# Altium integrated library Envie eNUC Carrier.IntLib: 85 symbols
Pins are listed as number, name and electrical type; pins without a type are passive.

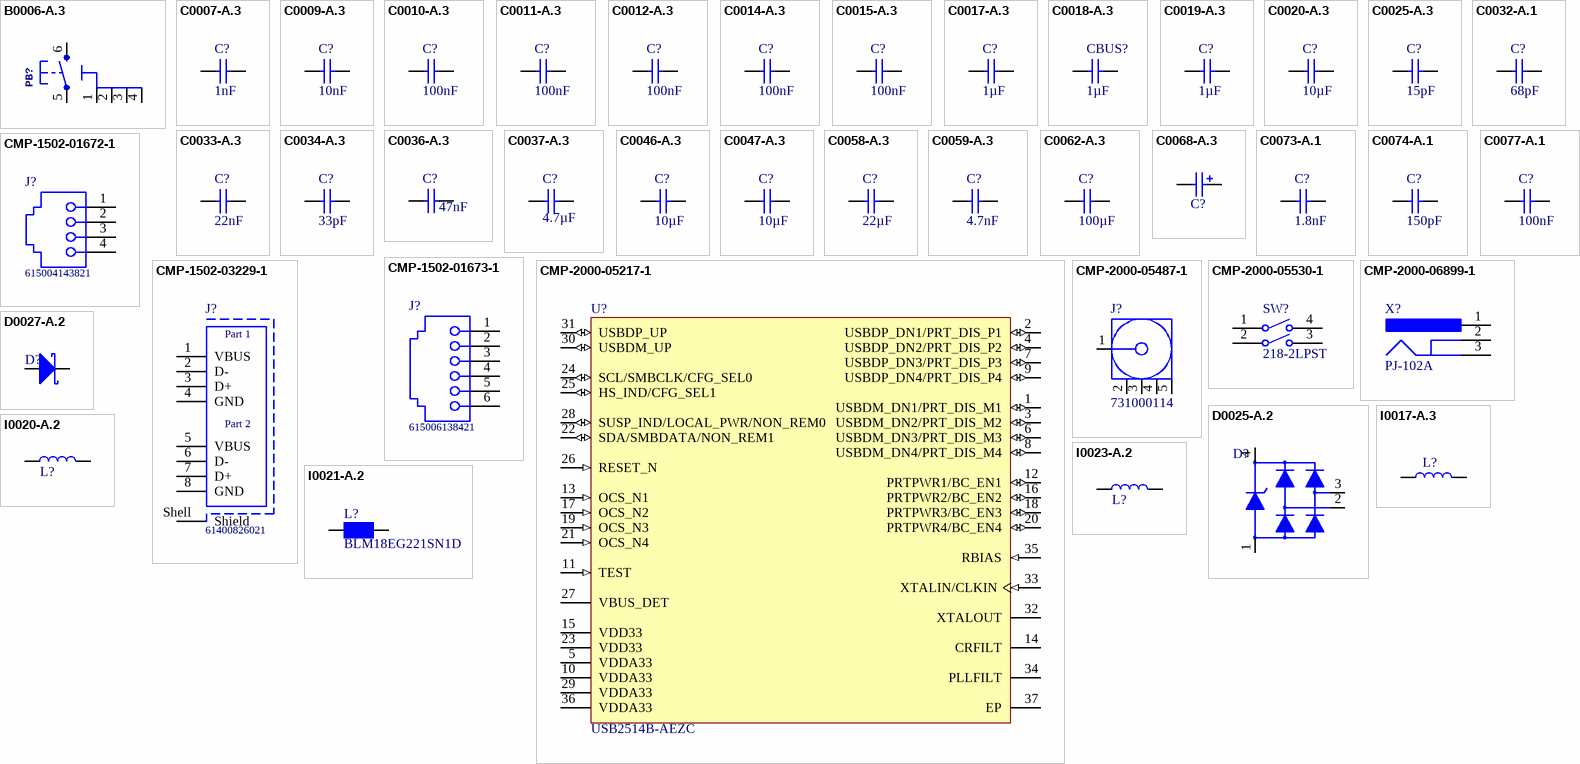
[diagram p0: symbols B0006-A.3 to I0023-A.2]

## B0006-A.3
designator PB?, comment PTS820J25KSMTRLFS  (value not drawn)
PUSHBUTTON SMD PTS820 NO HOLES; Manufacturer: C&K; Manufacturer: ITT C&K; Code Arduino: A5506; Actuator Type: Standard; Mechanical Life: 100000Cycles
footprint C&K_PTS820_NO_HOLES-1
pins: 1 (power), 2 (power), 3 (power), 4 (power), 5 1, 6 2

## C0007-A.3
designator C?, comment value 1nF  (hidden comment: C0402C100K5RACTU)
CAP CHIP 0402 1nF 50V X7R 10%; Manufacturer: KEMET; Manufacturer: Murata; Manufacturer Part Number: GRM155R71H102KA01D; Code Arduino: 2321
footprint CAP-0402 (Chip Capacitor, 2-Leads, Body  0402 (in) 1005 (mm), IPC Medium Density)
pins: 1, 2

## C0009-A.3
designator C?, comment value 10nF  (hidden comment: C0402C103K5RACTU)
CAP CHIP 0402 10nF 50V X7R 10%; Manufacturer: KEMET; Manufacturer: AVX; Manufacturer Part Number: 4025C103KAT2A; Code Arduino: 0165
footprint CAP-0402 (Chip Capacitor, 2-Leads, Body  0402 (in) 1005 (mm), IPC Medium Density)
pins: 1, 2

## C0010-A.3
designator C?, comment value 100nF  (hidden comment: C0402C104K8RACTU)
CAP CHIP 0402 100nF 10V X7R 10%; Manufacturer: AVX; Code Arduino: 0132
footprint CAP-0402 (Chip Capacitor, 2-Leads, Body  0402 (in) 1005 (mm), IPC Medium Density)
pins: 1, 2

## C0011-A.3
designator C?, comment value 100nF  (hidden comment: C0402C104K8PACTU)
CAP CHIP 0402 100nf 10V X5R 10%; Manufacturer: KEMET; Manufacturer: Kyocera AVX; Manufacturer Part Number: 0402ZD104KAT2A; Code Arduino: 0132
footprint CAP-0402 (Chip Capacitor, 2-Leads, Body  0402 (in) 1005 (mm), IPC Medium Density)
pins: 1, 2

## C0012-A.3
designator C?, comment value 100nF  (hidden comment: C0402C104K4RACTU)
CAP CHIP 0402 100nF 16V X7R 10%; Manufacturer: KEMET; Manufacturer: Kyocera AVX; Manufacturer Part Number: 0402YC104KAT2A; Code Arduino: 0132
footprint CAP-0402 (Chip Capacitor, 2-Leads, Body  0402 (in) 1005 (mm), IPC Medium Density)
pins: 1, 2

## C0014-A.3
designator C?, comment value 100nF  (hidden comment: C0402C104K3PACTU)
CAP CHIP 0402 100nF 25V X5R 10%; Manufacturer: KEMET; Manufacturer: Kyocera AVX; Manufacturer Part Number: 04023D104KAT2A; Code Arduino: 0132
footprint CAP-0402 (Chip Capacitor, 2-Leads, Body  0402 (in) 1005 (mm), IPC Medium Density)
pins: 1, 2

## C0015-A.3
designator C?, comment value 100nF  (hidden comment: GRM155R61H104KE19D)
CAP CHIP 0402 100nF 50V X5R 10%; Manufacturer: Murata; Code Arduino: A5141
footprint CAP-0402 (Chip Capacitor, 2-Leads, Body  0402 (in) 1005 (mm), IPC Medium Density)
pins: 1, 2

## C0017-A.3
designator C?, comment value 1µF  (hidden comment: C0402C105K8PACTU)
CAP CHIP 0402 1uF 10V X5R 10%; Manufacturer: KEMET; Manufacturer: AVX; Manufacturer Part Number: GRM155R61A105KE15D; Code Arduino: 0133
footprint CAP-0402 (Chip Capacitor, 2-Leads, Body  0402 (in) 1005 (mm), IPC Medium Density)
pins: 1, 2

## C0018-A.3
designator CBUS?, comment value 1µF  (hidden comment: C0402C105K4PACTU)
CAP CHIP 0402 1uF 16V X5R 10%; Manufacturer: KEMET; Manufacturer: Kyocera AVX; Manufacturer Part Number: 0402YD105KAT2A; Code Arduino: 0133
footprint CAP-0402 (Chip Capacitor, 2-Leads, Body  0402 (in) 1005 (mm), IPC Medium Density)
pins: 1, 2

## C0019-A.3
designator C?, comment value 1µF  (hidden comment: C0402C105M9PACTU)
CAP CHIP 0402 1uF 6V3 X5R 20%; Manufacturer: KEMET; Manufacturer: Kyocera AVX; Manufacturer Part Number: 04026D105MAT4A; Voltage: 6.3V; Code Arduino: 0133
footprint CAP-0402 (Chip Capacitor, 2-Leads, Body  0402 (in) 1005 (mm), IPC Medium Density)
pins: 1, 2

## C0020-A.3
designator C?, comment value 10µF  (hidden comment: GRM155R60G106ME44D)
CAP CHIP 0402 10UF 4V X5R 20%; Manufacturer: Murata; Code Arduino: 0132
footprint CAP-0402 (Chip Capacitor, 2-Leads, Body  0402 (in) 1005 (mm), IPC Medium Density)
pins: 1, 2

## C0025-A.3
designator C?, comment value 15pF  (hidden comment: C0402C150J5GACTU)
CAP CHIP 0402 15PF 50V C0G 5%; Manufacturer: Murata; Code Arduino: A5498
footprint CAP-0402 (Chip Capacitor, 2-Leads, Body  0402 (in) 1005 (mm), IPC Medium Density)
pins: 1, 2

## C0032-A.1
designator C?, comment value 68pF  (hidden comment: 04025A680JAT2A)
CAP CHIP 0402 68pF C0G 50V 5%; Manufacturer: AVX; Manufacturer: Kyocera AVX; Code Arduino: A5496
footprint CAP-0402 (Chip Capacitor, 2-Leads, Body  0402 (in) 1005 (mm), IPC Medium Density)
pins: 1, 2

## C0033-A.3
designator C?, comment value 22nF  (hidden comment: CL05B223KP5NNNC)
CAP CHIP 0402 22NF 10V X7R 10%; Manufacturer: Samsung Electro-Mechanics; Manufacturer: Samsung; Code Arduino: C0033
footprint CAP-0402 (Chip Capacitor, 2-Leads, Body  0402 (in) 1005 (mm), IPC Medium Density)
pins: 1, 2

## C0034-A.3
designator C?, comment value 33pF  (hidden comment: GRM1555C1H330JA01D)
CAP CHIP 0402 33PF 50V C0G 5%; Manufacturer: Murata; Code Arduino: A5494
footprint CAP-0402 (Chip Capacitor, 2-Leads, Body  0402 (in) 1005 (mm), IPC Medium Density)
pins: 1, 2

## C0036-A.3
designator C?, comment value 47nF  (hidden comment: GRM155R61H473KE14D)
CAP CHIP 0402 47nF 50V X5R 10%; Manufacturer: Murata; Code Arduino: 2216
footprint CAP-0402 (Chip Capacitor, 2-Leads, Body  0402 (in) 1005 (mm), IPC Medium Density)
pins: 1, 2

## C0037-A.3
designator C?, comment value 4.7µF  (hidden comment: GRM155R60J475ME47D)
CAP CHIP 0402 4.7uF 6V3 X5R 20%; Manufacturer: Murata; Code Arduino: 0833; Voltage: 6.3V
footprint CAP-0402 (Chip Capacitor, 2-Leads, Body  0402 (in) 1005 (mm), IPC Medium Density)
pins: 1, 2

## C0046-A.3
designator C?, comment value 10µF  (hidden comment: CC0603MRX5R5BB106)
CAP CHIP 0603 10uF 6V3 X5R 20% Bob; Manufacturer: Yageo; Voltage: 6.3V; Code Arduino: A5193
footprint CAP-0603 (Chip Capacitor, Body 0603 imperial,1.6x0.8mm, IPC High Density)
pins: 1, 2

## C0047-A.3
designator C?, comment value 10µF  (hidden comment: GRM188R61E106MA73J)
CAP CHIP 0603 10uF 25V X5R 20%; Manufacturer: Murata; Manufacturer: Samsung; Manufacturer Part Number: CL10A226MPCNUBE; Manufacturer Part Number: GRM188R61A226ME15D; Code Arduino: 2213
footprint CAP-0603 (Chip Capacitor, Body 0603 imperial,1.6x0.8mm, IPC High Density)
pins: 1, 2

## C0058-A.3
designator C?, comment value 22µF  (hidden comment: GRM219R61C226ME15K)
CAP CHIP 0805 22uF 16V X5R 20%; Manufacturer: Murata; Manufacturer: Samsung; Manufacturer Part Number: CL21A226MAQNNNE; Code Arduino: 2233
footprint CAP-0805 (Chip Capacitor, Body 0805 imperial, 2.0x1.2mm, IPC Medium Density)
pins: 1, 2

## C0059-A.3
designator C?, comment value 4.7nF  (hidden comment: C0805C472KDRACTU)
CAP CHIP 0805 4.7nF 1000V X7R 10%; Manufacturer: KEMET; Voltage: 1kV; Code Arduino: 0689
footprint CAP-0805 (Chip Capacitor, Body 0805 imperial, 2.0x1.2mm, IPC Medium Density)
pins: 1, 2

## C0062-A.3
designator C?, comment value 100µF  (hidden comment: CL31A107MPHNNNE)
CAP CHIP 1206 100UF 10V X5R 20%; Manufacturer: Samsung; Code Arduino: A5503
footprint CAP-1206 (Chip Capacitor, 2-Leads, 1206 (in) 3216 (mm), IPC Medium Density)
pins: 1, 2

## C0068-A.3
designator C?, comment EEE-FT1A151AR  (value not drawn)
CAP ALUM 150UF 20% 10V SMD; Manufacturer: Panasonic; Value: 150µF; Code Arduino: 2248
footprint PANASONIC_C
pins: 1, 2

## C0073-A.1
designator C?, comment value 1.8nF  (hidden comment: C0402C182J3GAC7867)
CAP CHIP 0402 1.8NF 25V C0G 5%; Manufacturer: KEMET; Manufacturer Part Number: C0402C182J3GACTU; Code Arduino: C0073
footprint CAP-0402 (Chip Capacitor, 2-Leads, Body  0402 (in) 1005 (mm), IPC Medium Density)
pins: 1, 2

## C0074-A.1
designator C?, comment value 150pF  (hidden comment: GRM1555C1H151FA01D)
CAP CHIP 0402 150PF 50V C0G 1%; Manufacturer: Murata; Code Arduino: C0074
footprint CAP-0402 (Chip Capacitor, 2-Leads, Body  0402 (in) 1005 (mm), IPC Medium Density)
pins: 1, 2

## C0077-A.1
designator C?, comment value 100nF  (hidden comment: TMK107BJ105MAHT)
CAP CHIP 0603 1UF 25V X5R 20%; Manufacturer: Taiyo Yuden; Code Arduino: C0077
footprint CAP-0603 (Chip Capacitor, Body 0603 imperial,1.6x0.8mm, IPC High Density)
pins: 1, 2

## CMP-1502-01672-1
designator J?, comment 615004143821
Modular Jack WR-MJ, Tab Up, Plastic, Horizontal Entry, THT, 4P4C; Manufacturer: Wurth Elektronik; Manufacturer: Wurth Electronics; Compliance: Leadfree/RoHS; Contact Resistance: 20mOhm; Withstanding Voltage: 1000VAC; Rated Current: 1.5A; Port: 1x1; Working Voltage: 120VAC
footprint 615004143821 (Modular Jack Horizontal Plastic 4P4C Tab Up)
pins: 1, 2, 3, 4

## CMP-1502-01673-1
designator J?, comment 615006138421
Modular Jack WR-MJ, Tab Up, Plastic, Horizontal Entry, THT, 6P6C; Manufacturer: Wurth Elektronik; Manufacturer: Wurth Electronics; Contact Resistance: 20mOhm; Working Voltage: 120VAC; Withstanding Voltage: 1000VAC; Compliance: Leadfree/RoHS; Rated Current: 1.5A; Port: 1x1
footprint 615006138421 (Modular Jack Horizontal Plastic 6P6C Tab Up)
pins: 1, 2, 3, 4, 5, 6

## CMP-1502-03229-1
designator J?, comment 61400826021
USB 2.0 Type A Receptacle WR-COM, Stacked Horizontal, THT; Manufacturer: Wurth Elektronik; Manufacturer: Wurth Electronics; Contact Resistance: 20mOhm; Rated Current: 1.5A; Working Voltage: 30VAC
footprint 61400826021 (USB 2.0 Type A Horizontal Dual Stacked)
pins: 1 VBUS, 2 D-, 3 D+, 4 GND, 5 VBUS, 6 D-, 7 D+, 8 GND, Shell Shield

## CMP-2000-05217-1
designator U?, comment USB2514B-AEZC
USB 2.0 High-Speed Hub Controller, 4 Ports, 3 to 3.6 V, 0 to 85 degC, 36-Pin QFN, RoHS, Tray; Manufacturer: Microchip; Interface: I²CEEPROM,SMBus(2-Wire,I²C); Other Names: 638-1122; Voltage - Supply: 3V~3.6V; Current - Supply: 70mA
footprint MCHP-QFN-36_V (QFN, 36-Leads, Body 6.00x6.00mm, Pitch 0.50mm, Thermal Pad 3.70x3.70mm)
pins: 1 USBDM_DN1/PRT_DIS_M1 (io), 2 USBDP_DN1/PRT_DIS_P1 (io), 3 USBDM_DN2/PRT_DIS_M2 (io), 4 USBDP_DN2/PRT_DIS_P2 (io), 5 VDDA33 (power) "3.3 V Analog Power", 6 USBDM_DN3/PRT_DIS_M3 (io), 7 USBDP_DN3/PRT_DIS_P3 (io), 8 USBDM_DN4/PRT_DIS_M4 (io), 9 USBDP_DN4/PRT_DIS_P4 (io), 10 VDDA33 (power) "3.3 V Analog Power", 11 TEST (in) "Test Pin: treat as a no connect pin or connect to ground. No trace or signal should be routed or attached to this pin.", 12 PRTPWR1/BC_EN1 (io), 13 OCS_N1 (in) "Over-Current Sense: input from external current monitor indicating an overcurrent condition.", 14 CRFILT "VDD Core Regulator Filter Capacitor: this pin can have up to a 0.1 uF low-ESR capacitor to VSS, or be left unconnected.", 15 VDD33 (power) "3.3 V Digital Power", 16 PRTPWR2/BC_EN2 (io), 17 OCS_N2 (in) "Over-Current Sense: input from external current monitor indicating an overcurrent condition.", 18 PRTPWR3/BC_EN3 (io), 19 OCS_N3 (in) "Over-Current Sense: input from external current monitor indicating an overcurrent condition.", 20 PRTPWR4/BC_EN4 (io), 21 OCS_N4 (in) "Over-Current Sense: input from external current monitor indicating an overcurrent condition.", 22 SDA/SMBDATA/NON_REM1 (io), 23 VDD33 (power) "3.3 V Digital Power", 24 SCL/SMBCLK/CFG_SEL0 (io), 25 HS_IND/CFG_SEL1 (io), 26 RESET_N (in) "RESET Input: the system can reset the chip by driving this input low. The minimum active low pulse is 1 us.", 27 VBUS_DET (power) "Detect Upstream VBUS Power: detects the state of the upstream VBUS power. The SMSC hub monitors VBUS_DET to determine when to assert the internal D+ pull-up resistor: (signaling a connect event). When designing a detachable (See Datasheet)", 28 SUSP_IND/LOCAL_PWR/NON_REM0 (io), 29 VDDA33 (power) "3.3 V Analog Power", 30 USBDM_UP (io) "USB Data: connect to the upstream USB bus data signals (host, port, or upstream hub).", 31 USBDP_UP (io) "USB Data: connect to the upstream USB bus data signals (host, port, or upstream hub).", 32 XTALOUT "Crystal Output: this is the other terminal of the crystal circuit with 1.2 V p-p output and a weak (< 1mA) driving strength. When an external clock source is used to drive XTALIN/CLKIN, leave this pin unconnected, or use (See Datasheet)", 33 XTALIN/CLKIN (in), 34 PLLFILT "PLL Regulator Filter Capacitor: this pin can have up to a 0.1 uF low-ESR capacitor to VSS, or be left unconnected.", 35 RBIAS (in) "USB Transceiver Bias: a 12.0 kohm (+/- 1%) resistor is attached from ground to this pin to set the transceiver’s internal bias settings.", 36 VDDA33 (power) "3.3 V Analog Power", 37 EP (power) "Ground Pad/ePad: the package slug is the only VSS for the device and must be tied to ground with multiple vias."

## CMP-2000-05487-1
designator J?, comment 731000114
SMA Right-Angle PCB Jack Receptacle, Brass Body, Gold Plated, 50 Ohm, 5-Pin THD, RoHS, Tray; Manufacturer: Molex; Manufacturer Part Number: 73100-0114
footprint MOLX-731000114_V (Connector, 5-Leads, Body 14.8x6.35mm, Pitch 2.54mm)
pins: 1, 2, 3, 4, 5

## CMP-2000-05530-1
designator SW?, comment 218-2LPST
Half Pitch DIP Switch Auto Placeable, 25 mA, 24 V, -55 to 85 degC, 4-Pin SMD, RoHS, Tube; Manufacturer: CTS Corporation; Manufacturer: CTS; Voltage Rating: 24VDC; Number of Positions: 2; Online Catalog: 218Series; Actuator Type: Slide(Standard); Washable: Yes; Pitch: 0.050"(1.27mm),Half; 3D Model: 218Series2Pole.stp; Catalog Drawings: 218-2218SeriesFootprint218SeriesEnd; Other Names: 2182LPSTCT2182LPST; Electrical Life: 1,000Cycles; Current Rating: 25mA; Actuator Level: Flush,Recessed; Circuit: SPST
footprint CTS-218-2LPST_V (SMD, 4-Leads, Body 5.8x3.71mm, Pitch 1.27mm)
pins: 1, 2, 3, 4

## CMP-2000-06899-1
designator X?, comment PJ-102A
DC Power Jack, 2.5 A, -25 to 85 degC, 3-Pin THD, RoHS; Manufacturer 1: CUIInc.; Insulation Resistance: 50MOhms; Current Rating: 2.5A; Inside Contact Diameter: 2mm; Outside Contact Diameter: 6.5mm; Brand: CUI; Mounting Angle: Right; Voltage Rating: 24V
footprint CUI-PJ-102A_V (THD, 3-Leads, Body 14.4x9mm, Pitch 3mm)
pins: 1, 2, 3

## D0025-A.2
designator D?, comment Diode TVS array  (value not drawn)
TVS ARRAY 4LIN.8kV 1pF SOT143B; Manufacturer: Nexperia; Part Number: PRTR5V0U2X,215; Device Type: ESD protection; Code Arduino: 2209
footprint SOT190P230X110-4N
pins: 1, 2, 3, 4

## D0027-A.2
designator D?, comment PESD0402-140CT-ND  (value not drawn)
DIODE TVS SMD 0402 14V 40V; Manufacturer: Littelfuse Inc; Code Arduino: 2280; Device Type: ESD protection
footprint 0402 (Chip Resistor, 2-Leads, Body  0402 (in) 1005 (mm), IPC Medium Density)
pins: A, C

## I0017-A.3
designator L?, comment SRP4020TA-2R2M  (value not drawn)
IND FIXED 2.2UH 4A 61 MOHM SMD; Manufacturer: Bourns; Code Arduino: 2218; Device Type: Inductor
footprint SRP4020
pins: 1, 2

## I0020-A.2
designator L?, comment LQG15HS68NJ02D  (value not drawn)
IND CHIP 0402 68NH 250MA 5%; Manufacturer: Murata; Device Type: Inductor; Code Arduino: A5499
footprint 0402 (Chip Inductor, 2-Leads, Body  0402 (in) 1005 (mm), IPC Medium Density)
pins: 1, 2

## I0021-A.2
designator L?, comment BLM18EG221SN1D
FERRITE SMD 0603 220 OHM 2A; Manufacturer: Murata; Impedance: 220µH; Code Arduino: A5489; Test Frequency: 100MHz; Tolerance: 25%; DC Resistance (DCR): 50mR
footprint L-0603 (Chip Inductor - Body 0603 imperial,1.6x0.8mm, IPC High Density)
pins: 1, 2

## I0023-A.2
designator L?, comment LQG15HN39NJ02D  (value not drawn)
IND CHIP 0402 39NH; Manufacturer: Murata; Code Arduino: A5497; Current: 250mA; Device Type: Inductor
footprint 0402 (Chip Inductor, 2-Leads, Body  0402 (in) 1005 (mm), IPC Medium Density)
pins: 1, 2

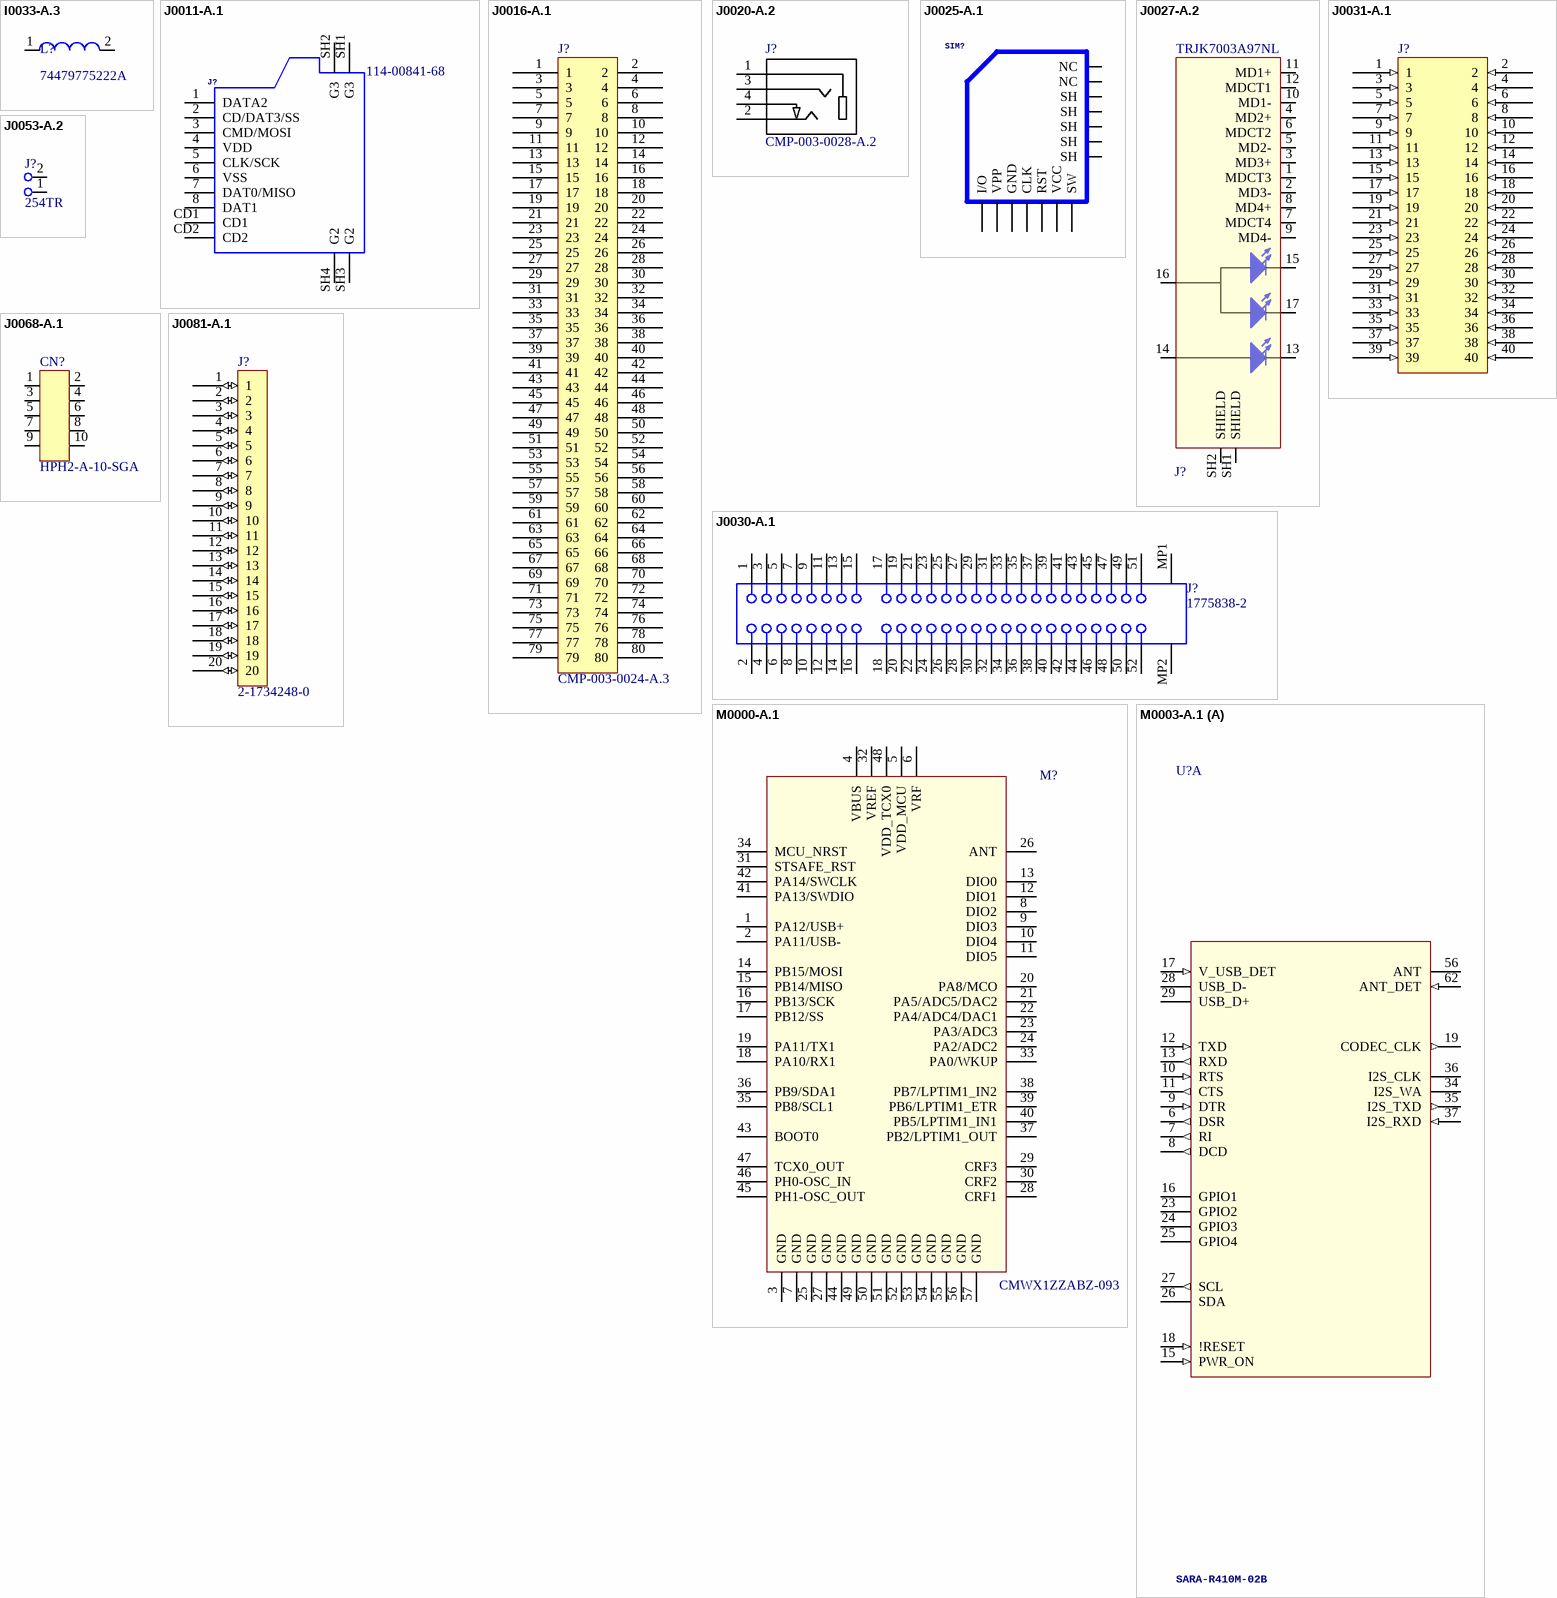
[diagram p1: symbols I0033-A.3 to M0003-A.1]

## I0033-A.3
designator L?, comment 74479775222A
IND FIXED 2.2UH; Manufacturer: Wurth Electronics; Manufacturer: Bourns; Manufacturer Part Number: CVH201205-2R2M; Device Type: Inductor; Code Arduino: I0033
footprint INDC2314X10N (Chip Inductor, 2-Leads, Body 2,35x1,45mm, IPC Medium Density)
pins: 1, 2

## J0011-A.1
designator J?, comment 114-00841-68
CONN Micro SD; Manufacturer: Amphenol; Manufacturer: Amphenol Commercial; Manufacturer Part Number: 1140084168; Code Arduino: A5328
footprint AMPHENOL_114-00841-68
pins: 1 DATA2, 2 CD/DAT3/SS, 3 CMD/MOSI, 4 VDD (power), 5 CLK/SCK, 6 VSS (power), 7 DAT0/MISO, 8 DAT1, CD1, CD2, SH1 G3, SH2 G3, SH3 G2, SH4 G2

## J0016-A.1
designator J?, comment CMP-003-0024-A.3
CONN RCPT 80POS 0.4MM SMD GOLD; Gender: Receptacle
footprint DF40HC(3.5)-80DS-0.4V(51)-Footprint-1
pins: 1, 2, 3, 4, 5, 6, 7, 8, 9, 10, 11, 12, 13, 14, 15, 16, 17, 18, 19, 20, 21, 22, 23, 24, 25, 26, 27, 28, 29, 30, 31, 32, 33, 34, 35, 36, 37, 38, 39, 40, 41, 42, 43, 44, 45, 46, 47, 48, 49, 50, 51, 52, 53, 54, 55, 56, 57, 58, 59, 60, 61, 62, 63, 64, 65, 66, 67, 68, 69, 70, 71, 72, 73, 74, 75, 76, 77, 78, 79, 80

## J0020-A.2
designator J?, comment CMP-003-0028-A.2
CONN JACK STEREO 3.5MM SMD R/A; Manufacturer: CUI; Manufacturer Part Number: SJ-3524-SMT-TR; Gender: Female; Code Arduino: J0020
footprint SJ-3524-SMT-TR-Footprint-1
pins: 1, 2, 3, 4

## J0025-A.1
designator SIM?, comment 2199337-5  (value not drawn)
CONN MICROSIM CARD HOLDER; Manufacturer: TE; Manufacturer: TE Connectivity AMP; Code Arduino: A5504
footprint MICROSIM8
pins: CLK, GND, IO I/O, NC1 NC, NC2 NC, RST, SH1 SH, SH2 SH, SH3 SH, SH4 SH, SH5 SH, SW, VCC, VPP

## J0027-A.2
designator J?, comment TRJK7003A97NL
CONN ETHERNET 1GIGABIT; Manufacturer: TRXCOM; Code Arduino: J0027
footprint TRJK0071AWNL -Footprint-2
pins: 1 MDCT3, 2 MD3-, 3 MD3+, 4 MD2+, 5 MD2-, 6 MDCT2, 7 MDCT4, 8 MD4+, 9 MD4-, 10 MD1-, 11 MD1+, 12 MDCT1, 13, 14, 15, 16, 17, SH1 SHIELD, SH2 SHIELD

## J0030-A.1
designator J?, comment 1775838-2
CONN PCI EXP MINI FEMALE 52POS; Manufacturer: TE Connectivity; Manufacturer: TE Connectivity AMP; Code Arduino: J0030; PCB Mount Retention: Without; Connector Type: Receptacle; High Temperature Housing: Yes; Stackable: No; PCB Mounting Orientation: Vertical; Pitch: 0.8mm; Stack Height: 5.6mm; Row Spacing: 0.031inch; Number of Positions: 52
footprint 1775838-2-Footprint-1
pins: 1, 2, 3, 4, 5, 6, 7, 8, 9, 10, 11, 12, 13, 14, 15, 16, 17, 18, 19, 20, 21, 22, 23, 24, 25, 26, 27, 28, 29, 30, 31, 32, 33, 34, 35, 36, 37, 38, 39, 40, 41, 42, 43, 44, 45, 46, 47, 48, 49, 50, 51, 52, MP1 53, MP2 54

## J0031-A.1
designator J?, comment CMP-003-0051-A.3  (value not drawn)
CONN BOARD STACKER HDR 40 POS 1.27mm ST SMD; Manufacturer: Samtec; Manufacturer Part Number: FW-20-05-G-D-254-150; Gender: Male
footprint FW-20-05-G-D-254-150-Footprint-1
pins: 1 (in), 2 (in), 3 (in), 4 (in), 5 (in), 6 (in), 7 (in), 8 (in), 9 (in), 10 (in), 11 (in), 12 (in), 13 (in), 14 (in), 15 (in), 16 (in), 17 (in), 18 (in), 19 (in), 20 (in), 21 (in), 22 (in), 23 (in), 24 (in), 25 (in), 26 (in), 27 (in), 28 (in), 29 (in), 30 (in), 31 (in), 32 (in), 33 (in), 34 (in), 35 (in), 36 (in), 37 (in), 38 (in), 39 (in), 40 (in)

## J0053-A.2
designator J?, comment 254TR
CONN BATTERY HOLDER 18650 CLIP SMT; Manufacturer: Keystone Electronics; Code Arduino: J0053
footprint 254TR-Footprint-1
pins: 1 -, 2 GND

## J0068-A.1
designator CN?, comment HPH2-A-10-SGA
CONN CONN STRIP 1,27 M/2/D 10v AuF H6,3; Manufacturer: Adam Tech; Code Arduino: 0171
footprint PINHEAD_2X05_127
pins: 1, 2, 3, 4, 5, 6, 7, 8, 9, 10

## J0081-A.1
designator J?, comment 2-1734248-0
CONN FPC VERT 20POS 1.00MM SMD; Manufacturer: TE Connectivity; Contact Location: Bottom; PCB Mounting Orientation: Vertical; Sealable: No (Without); Shielding: Unshielded; Wire/Cable Type: Flat Flex; Number of Contacts: 20; Code Arduino: J0081; PCB Mount Retention: With; Pitch: 0.039inch; Voltage Rating: 125V; Connector Type: Receptacle,Connector,Socket; Contact Current Rating: 1A; Shrouded: Yes (With); Gender: Male; Connector System: Flex-to-Board
footprint 2-1734248-0-Footprint-1
pins: 1 (io), 2 (io), 3 (io), 4 (io), 5 (io), 6 (io), 7 (io), 8 (io), 9 (io), 10 (io), 11 (io), 12 (io), 13 (io), 14 (io), 15 (io), 16 (io), 17 (io), 18 (io), 19 (io), 20 (io)

## M0000-A.1
designator M?, comment CMWX1ZZABZ-093
MODULE LoRa; Manufacturer: Murata; Code Arduino: A5491
footprint CMWX1ZZABZ
pins: 1 PA12/USB+, 2 PA11/USB-, 3 GND, 4 VBUS, 5 VDD_MCU, 6 VRF, 7 GND, 8 DIO2, 9 DIO3, 10 DIO4, 11 DIO5, 12 DIO1, 13 DIO0, 14 PB15/MOSI, 15 PB14/MISO, 16 PB13/SCK, 17 PB12/SS, 18 PA10/RX1, 19 PA11/TX1, 20 PA8/MCO, 21 PA5/ADC5/DAC2, 22 PA4/ADC4/DAC1, 23 PA3/ADC3, 24 PA2/ADC2, 25 GND, 26 ANT, 27 GND, 28 CRF1, 29 CRF3, 30 CRF2, 31 STSAFE_RST, 32 VREF, 33 PA0/WKUP, 34 MCU_NRST, 35 PB8/SCL1, 36 PB9/SDA1, 37 PB2/LPTIM1_OUT, 38 PB7/LPTIM1_IN2, 39 PB6/LPTIM1_ETR, 40 PB5/LPTIM1_IN1, 41 PA13/SWDIO, 42 PA14/SWCLK, 43 BOOT0, 44 GND, 45 PH1-OSC_OUT, 46 PH0-OSC_IN, 47 TCX0_OUT, 48 VDD_TCX0, 49 GND, 50 GND, 51 GND, 52 GND, 53 GND, 54 GND, 55 GND, 56 GND, 57 GND

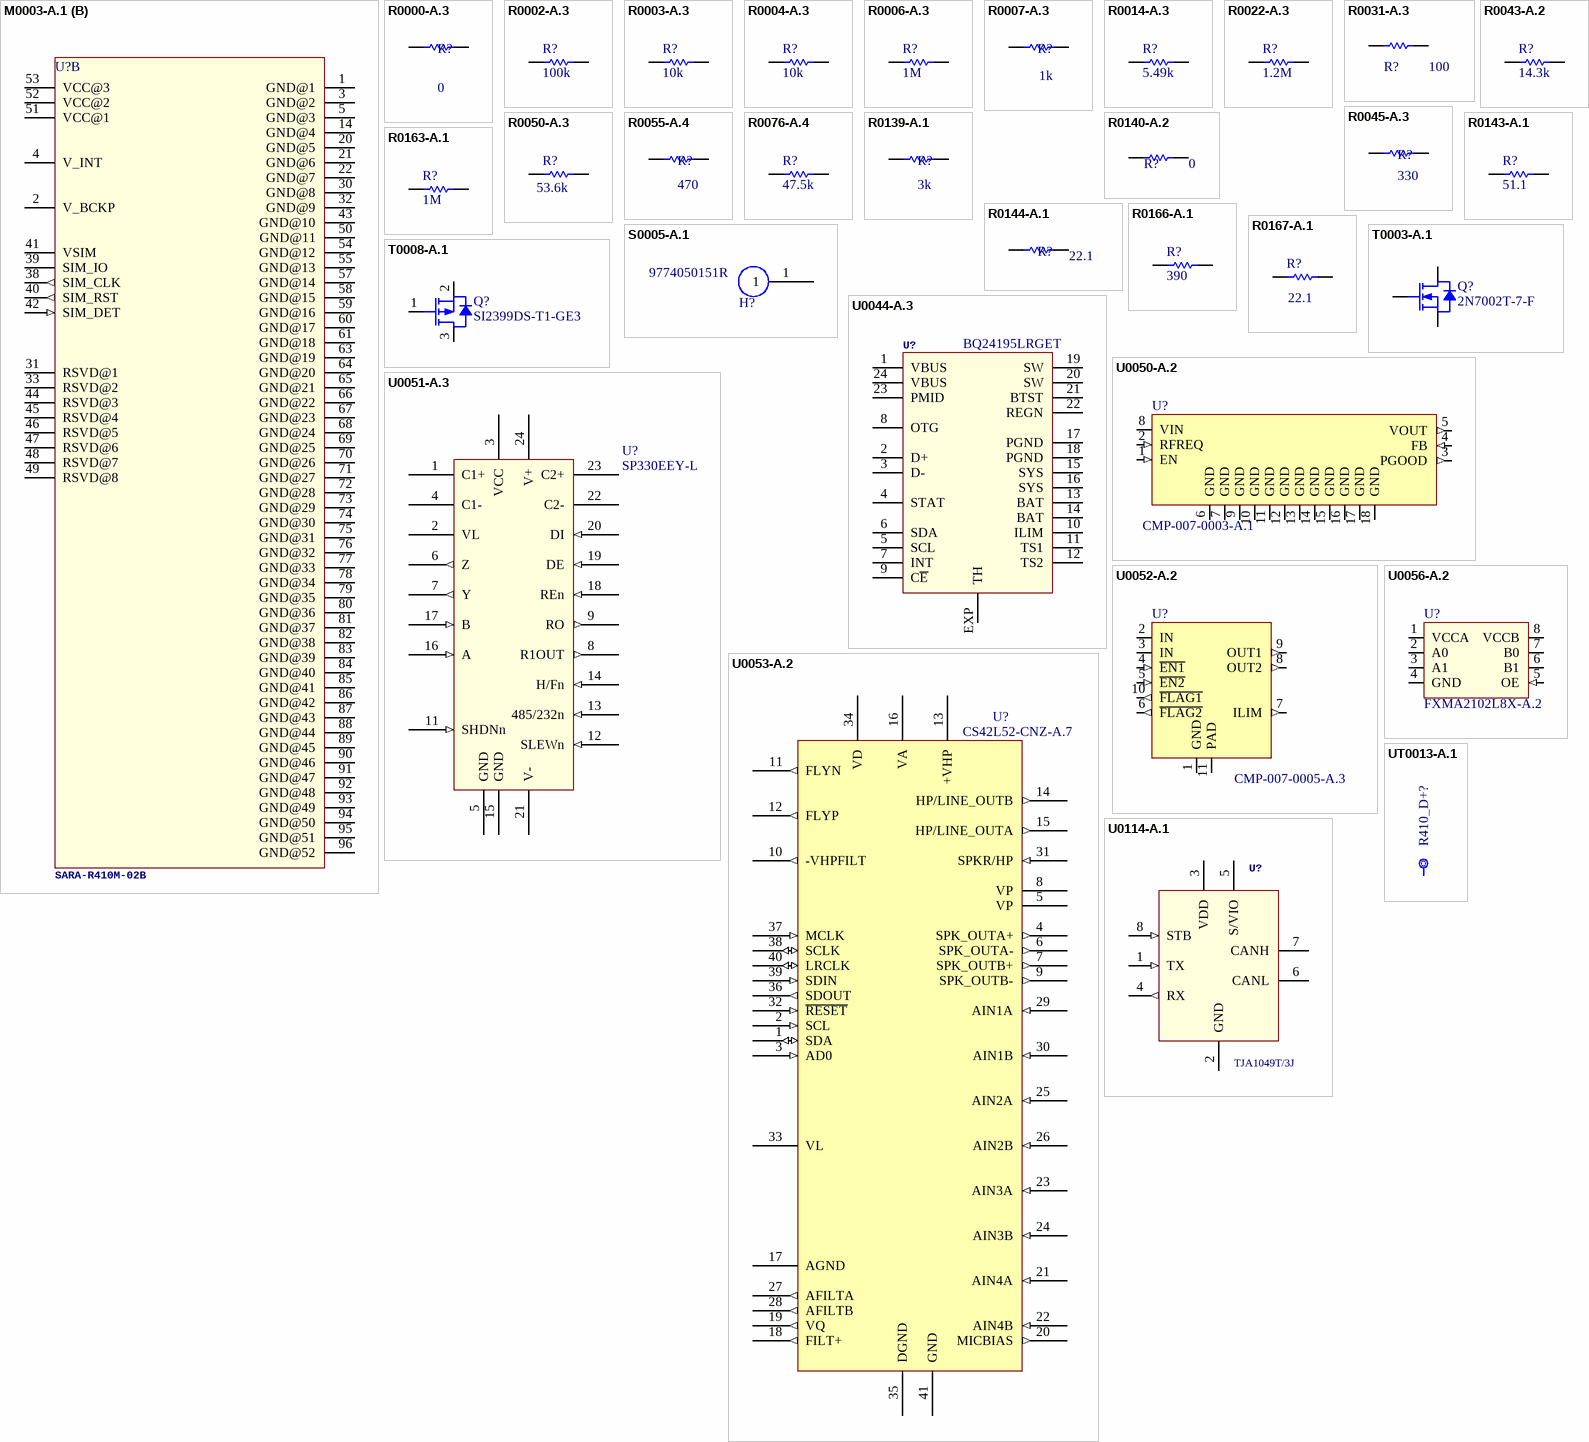
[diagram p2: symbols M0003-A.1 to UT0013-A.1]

## M0003-A.1
designator U?, comment SARA-R410M-02B
MODULE RF TXRX CELL 4G LTE CATM1/NB-IOT; Manufacturer: UBlox; Manufacturer: u-blox
footprint SARA-96
part A pins: 6 DSR (out), 7 RI (out), 8 DCD (out), 9 DTR (in), 10 RTS (in), 11 CTS (out), 12 TXD (in), 13 RXD (out), 15 PWR_ON (in), 16 GPIO1, 17 V_USB_DET (in), 18 !RESET (in), 19 CODEC_CLK (out), 23 GPIO2, 24 GPIO3, 25 GPIO4, 26 SDA, 27 SCL (out), 28 USB_D-, 29 USB_D+, 34 I2S_WA, 35 I2S_TXD (out), 36 I2S_CLK, 37 I2S_RXD (in), 56 ANT, 62 ANT_DET (in)
part B pins: 1 GND@1 (power), 2 V_BCKP (power), 3 GND@2 (power), 4 V_INT (power), 5 GND@3 (power), 14 GND@4 (power), 20 GND@5 (power), 21 GND@6 (power), 22 GND@7 (power), 30 GND@8 (power), 31 RSVD@1, 32 GND@9 (power), 33 RSVD@2, 38 SIM_CLK (out), 39 SIM_IO, 40 SIM_RST (out), 41 VSIM (power), 42 SIM_DET (in), 43 GND@10 (power), 44 RSVD@3, 45 RSVD@4, 46 RSVD@5, 47 RSVD@6, 48 RSVD@7, 49 RSVD@8, 50 GND@11 (power), 51 VCC@1 (power), 52 VCC@2 (power), 53 VCC@3 (power), 54 GND@12 (power), 55 GND@13 (power), 57 GND@14 (power), 58 GND@15 (power), 59 GND@16 (power), 60 GND@17 (power), 61 GND@18 (power), 63 GND@19 (power), 64 GND@20 (power), 65 GND@21 (power), 66 GND@22 (power), 67 GND@23 (power), 68 GND@24 (power), 69 GND@25 (power), 70 GND@26 (power), 71 GND@27 (power), 72 GND@28 (power), 73 GND@29 (power), 74 GND@30 (power), 75 GND@31 (power), 76 GND@32 (power), 77 GND@33 (power), 78 GND@34 (power), 79 GND@35 (power), 80 GND@36 (power), 81 GND@37 (power), 82 GND@38 (power), 83 GND@39 (power), 84 GND@40 (power), 85 GND@41 (power), 86 GND@42 (power), 87 GND@43 (power), 88 GND@44 (power), 89 GND@45 (power), 90 GND@46 (power), 91 GND@47 (power), 92 GND@48 (power), 93 GND@49 (power), 94 GND@50 (power), 95 GND@51 (power), 96 GND@52 (power)

## R0000-A.3
designator R?, comment value 0  (hidden comment: CRCW04020000Z0EDC)
RES CHIP 0402 0R 1/16W; Manufacturer: Vishay; Manufacturer: Panasonic; Manufacturer Part Number: ERJ-S020R00X; Code Arduino: 0039; Tolerance: J; Power: 63mW
footprint RES-0402 (Chip Resistor, 2-Leads, Body  0402 (in) 1005 (mm), IPC Medium Density)
pins: 1, 2

## R0002-A.3
designator R?, comment value 100k  (hidden comment: CRCW0402100KJNED)
RES CHIP 0402 100K 5% 1/16W; Manufacturer: Vishay; Manufacturer: Panasonic; Manufacturer Part Number: ERJ-2GEJ104X; Power: 63mW; Code Arduino: 0134
footprint RES-0402 (Chip Resistor, 2-Leads, Body  0402 (in) 1005 (mm), IPC Medium Density)
pins: 1, 2

## R0003-A.3
designator R?, comment value 10k  (hidden comment: CRCW040210K0FKED)
RES CHIP 0402 10K 1% 1/16W; Manufacturer: Vishay; Manufacturer Part Number: CRCW0402-10K0FKED; Manufacturer: Panasonic; Manufacturer Part Number: ERJ-2RKF1002X; Power: 63mW; Code Arduino: 0136
footprint RES-0402 (Chip Resistor, 2-Leads, Body  0402 (in) 1005 (mm), IPC Medium Density)
pins: 1, 2

## R0004-A.3
designator R?, comment value 10k  (hidden comment: CRCW040210K0JNED)
RES CHIP 0402 10K 5% 1/16W; Manufacturer: Vishay; Manufacturer: Vishay Dale; Manufacturer: Panasonic; Manufacturer Part Number: ERJ-2GEJ103X; Code Arduino: 0136; Power: 63mW
footprint RES-0402 (Chip Resistor, 2-Leads, Body  0402 (in) 1005 (mm), IPC Medium Density)
pins: 1, 2

## R0006-A.3
designator R?, comment value 1M  (hidden comment: CRCW04021M00JNED)
RES CHIP 0402 1M 5% 1/16W; Manufacturer: Panasonic; Manufacturer Part Number: ERJ-2GEJ105X; Code Arduino: 0139; Power: 63mW
footprint RES-0402 (Chip Resistor, 2-Leads, Body  0402 (in) 1005 (mm), IPC Medium Density)
pins: 1, 2

## R0007-A.3
designator R?, comment value 1k  (hidden comment: CRCW04021K00FKEDC)
RES CHIP 0402 1K 1% 1/16W; Manufacturer: Vishay; Manufacturer: Panasonic; Manufacturer Part Number: ERJ-2RKF1001X; Power: 63mW; Code Arduino: 0140
footprint RES-0402 (Chip Resistor, 2-Leads, Body  0402 (in) 1005 (mm), IPC Medium Density)
pins: 1, 2

## R0014-A.3
designator R?, comment value 5.49k  (hidden comment: CRCW04025K49FKED)
RES CHIP 0402 5K49 1% 1/16W; Manufacturer: Vishay; Manufacturer: Panasonic; Manufacturer Part Number: ERJ-2RKF5491X; Code Arduino: 2197; Power: 63mW
footprint RES-0402 (Chip Resistor, 2-Leads, Body  0402 (in) 1005 (mm), IPC Medium Density)
pins: 1, 2

## R0022-A.3
designator R?, comment value 1.2M  (hidden comment: CRCW04021M20JNED)
RES CHIP 0402 1M2 5% 1/16W; Manufacturer: Vishay; Manufacturer: Panasonic; Manufacturer Part Number: ERJ-2GEJ125X; Manufacturer: Vishay Dale; Code Arduino: 2352; Power: 63mW
footprint RES-0402 (Chip Resistor, 2-Leads, Body  0402 (in) 1005 (mm), IPC Medium Density)
pins: 1, 2

## R0031-A.3
designator R?, comment value 100  (hidden comment: CRCW0402100RFKED)
RES CHIP 0402 100R 1% 1/16W; Manufacturer: Vishay; Manufacturer: Panasonic; Manufacturer Part Number: ERJ-2RKF1000X; Manufacturer: Vishay Dale; Power: 63mW; Code Arduino: A5359
footprint RES-0402 (Chip Resistor, 2-Leads, Body  0402 (in) 1005 (mm), IPC Medium Density)
pins: 1, 2

## R0043-A.2
designator R?, comment value 14.3k  (hidden comment: CRCW040214K3FKED)
RES CHIP 0402 14K3 1/16W 1%; Manufacturer: Vishay; Manufacturer: Panasonic; Manufacturer Part Number: ERJ-2RKF1432X; Power: 63mW; Code Arduino: R0043
footprint RES-0402 (Chip Resistor, 2-Leads, Body  0402 (in) 1005 (mm), IPC Medium Density)
pins: 1, 2

## R0045-A.3
designator R?, comment value 330  (hidden comment: CRCW0402330RJNED)
RES CHIP 0402 330R 5% 1/16W; Manufacturer: Vishay; Manufacturer: Panasonic; Manufacturer Part Number: ERJ-2GEJ331X; Manufacturer: Vishay Dale; Code Arduino: 2229; Power: 63mW
footprint RES-0402 (Chip Resistor, 2-Leads, Body  0402 (in) 1005 (mm), IPC Medium Density)
pins: 1, 2

## R0050-A.3
designator R?, comment value 53.6k  (hidden comment: CRCW040253K6FKED)
RES CHIP 0402 53.6K 1% 1/16W; Manufacturer: Vishay; Manufacturer: Panasonic; Manufacturer Part Number: ERJ-2RKF5362X; Power: 63mW; Code Arduino: A5313
footprint RES-0402 (Chip Resistor, 2-Leads, Body  0402 (in) 1005 (mm), IPC Medium Density)
pins: 1, 2

## R0055-A.4
designator R?, comment value 470  (hidden comment: CRCW0402470RJNED)
RES CHIP 0402 470R 5% 1/16W; Manufacturer: Vishay; Manufacturer: Vishay Dale; Manufacturer: Panasonic; Manufacturer Part Number: ERJ-2GEJ471X; Power: 63mW; Code Arduino: R0055; Tolerance: 1%
footprint RES-0402 (Chip Resistor, 2-Leads, Body  0402 (in) 1005 (mm), IPC Medium Density)
pins: 1, 2

## R0076-A.4
designator R?, comment value 47.5k  (hidden comment: CRCW040247K5FKED)
RES CHIP 0402 47K5 1% 1/16W; Manufacturer: Vishay; Manufacturer: Panasonic; Manufacturer Part Number: ERJ-2RKF4752X; Power: 63mW; Code Arduino: R0076
footprint RES-0402 (Chip Resistor, 2-Leads, Body  0402 (in) 1005 (mm), IPC Medium Density)
pins: 1, 2

## R0139-A.1
designator R?, comment value 3k  (hidden comment: CRCW04023K00JNED)
RES CHIP 0402 3k 5% 1/16W; Manufacturer: Vishay; Manufacturer: Vishay Dale; Manufacturer: Panasonic; Manufacturer Part Number: ERJ-2GEJ302X; Tolerance: 1%; Power: 63mW; Code Arduino: R0139
footprint RES-0402 (Chip Resistor, 2-Leads, Body  0402 (in) 1005 (mm), IPC Medium Density)
pins: 1, 2

## R0140-A.2
designator R?, comment value 0  (hidden comment: CRCW02010000Z0ED)
RES CHIP 0201 0R 1/20W 5%; Manufacturer: Vishay; Code Arduino: R0140; Power: 50mW
footprint RES-0201 (Chip Resistor, 2-Leads, Body 0201 (in) 0603 (mm) IPC Medium Density)
pins: 1, 2

## R0143-A.1
designator R?, comment value 51.1  (hidden comment: CRCW040251R1FKED)
RES CHIP 0402 51R1 1% 1/16W; Manufacturer: Yageo; Manufacturer: Panasonic; Manufacturer Part Number: ERJ-2RKF51R1X; Manufacturer: Vishay; Manufacturer Part Number: CRCW04025-1R1FKED; Power: 63mW; Code Arduino: R0143
footprint RES-0402 (Chip Resistor, 2-Leads, Body  0402 (in) 1005 (mm), IPC Medium Density)
pins: 1, 2

## R0144-A.1
designator R?, comment value 22.1  (hidden comment: CRCW040222R1FKED)
RES CHIP 0402 22R1 1% 1/16W; Manufacturer: Vishay; Manufacturer: Panasonic; Manufacturer Part Number: ERJ-2RKF2212X; Power: 63mW; Code Arduino: R0144
footprint RES-0402 (Chip Resistor, 2-Leads, Body  0402 (in) 1005 (mm), IPC Medium Density)
pins: 1, 2

## R0163-A.1
designator R?, comment value 1M  (hidden comment: CRCW06031M00FKEA)
RES CHIP 0603 1M 1% 1/10W; Manufacturer: Vishay; Manufacturer: Panasonic; Manufacturer Part Number: ERJ-3EKF1004V; Power: 100mW; Code Arduino: R0163
footprint RES-0603 (Chip Resistor - Body 0603 imperial,1.6x0.8mm, IPC High Density)
pins: 1, 2

## R0166-A.1
designator R?, comment value 390  (hidden comment: CRCW04022K00JNED)
RES CHIP 0402 2K 5% 1/16W; Manufacturer: Vishay; Manufacturer: Panasonic; Manufacturer Part Number: ERJ-2GEJ202X; Manufacturer: Vishay Dale; Tolerance: 1%; Power: 63mW; Code Arduino: R0166
footprint RES-0402 (Chip Resistor, 2-Leads, Body  0402 (in) 1005 (mm), IPC Medium Density)
pins: 1, 2

## R0167-A.1
designator R?, comment value 22.1  (hidden comment: RR0510P-123-D)
RES CHIP 0402 12K 0.5% 1/16W; Manufacturer: Susumu; Code Arduino: R0167; Power: 63mW
footprint RES-0402 (Chip Resistor, 2-Leads, Body  0402 (in) 1005 (mm), IPC Medium Density)
pins: 1, 2

## S0005-A.1
designator H?, comment 9774050151R
VERT STANDOFF SMD M2.5X0.45 STEEL 5MM; Manufacturer: Würth Elektronik; Manufacturer: Wurth Electronics; Threaded/Unthreaded: Threaded; Plating: Tin; Code Arduino: S0005; Outside Diameter: 0.201inch
footprint 9774050151R-Footprint-1
pins: 1

## T0003-A.1
designator Q?, comment 2N7002T-7-F
MOSFET N-CH 60V 115mA SOT523; Manufacturer: Diodes Inc.; Manufacturer: Diodes; Code Arduino: 2368; Device Type: Mosfet N-CH SMD
footprint SOT523
pins: D, G, S

## T0008-A.1
designator Q?, comment SI2399DS-T1-GE3
MOSFET P-CH 20V 6A SOT-23; Device Type: Mosfet P-CH SMD; Code Arduino: A5270
footprint SOT23
pins: 1 G, 2 S, 3 D

## U0044-A.3
designator U?, comment Part Number: BQ24195LRGET  (hidden comment: BQ24195LRGET-A.4)
IC BATT.CHRG.CTRL. VQFN24; Manufacturer: Texas Instruments; Code Arduino: 2201
footprint VQFN24
pins: 1 VBUS, 2 D+, 3 D-, 4 STAT, 5 SCL, 6 SDA, 7 INT, 8 OTG, 9 C~{E}, 10 ILIM, 11 TS1, 12 TS2, 13 BAT, 14 BAT, 15 SYS, 16 SYS, 17 PGND, 18 PGND, 19 SW, 20 SW, 21 BTST, 22 REGN, 23 PMID, 24 VBUS, EXP TH

## U0050-A.2
designator U?, comment CMP-007-0003-A.1
IC DC/DC POWER MODULE 36V 5A LGA18; Part Number: MPM3550E; Manufacturer: MPS; Code Arduino: U0050
footprint LGA18C100P6X4_1200X1200X360 (LGA, 18-Leads, Body 12.00x12.00mmx3.60mm, Pitch 1.00mm)
pins: 1 EN (in), 2 RFREQ (in), 3 PGOOD (out), 4 FB (in), 5 VOUT (out), 6 GND (power), 7 GND (power), 8 VIN (power), 9 GND (power), 10 GND (power), 11 GND (power), 12 GND (power), 13 GND (power), 14 GND (power), 15 GND (power), 16 GND (power), 17 GND (power), 18 GND (power)

## U0051-A.3
designator U?, comment Part Number: SP330EEY-L  (hidden comment: CMP-007-0004-A.4)
IC TXRX RS232/485 24TSSOP; Manufacturer: Maxlinear; Simplex/Duplex: Full Duplex; Data Rate: 20Mbps; Receiver Hysteresis: 25mV; Code Arduino: U0051; Device Type: Transceiver
footprint TSOP65P640X120-24N (TSOP, 24-Leads, Body 7,80x4,40mm, Pitch 0,65mm, IPC Medium Density)
pins: 1 C1+ (power), 2 VL (power), 3 VCC (power), 4 C1- (power), 5 GND (power), 6 Z (out), 7 Y (out), 8 R1OUT (out), 9 RO (out), 11 SHDNn (in), 12 SLEWn (in), 13 485/232n (in), 14 H/Fn (in), 15 GND (power), 16 A (in), 17 B (in), 18 REn (in), 19 DE (in), 20 DI (in), 21 V- (power), 22 C2- (power), 23 C2+ (power), 24 V+ (power)

## U0052-A.2
designator U?, comment CMP-007-0005-A.3
IC POWER SWITCH DUAL CHANNEL OCP; Manufacturer: ON Semiconductor; Part Number: NCP383LMUAJAATXG; Max Input Voltage: 5.5V; Min Input Voltage: 2.7V; Turn-Off Delay Time: 3ms; Number of Outputs: 2; Output Configuration: High Side; Turn-On Delay Time: 9ms; Interface: On/Off; Max Power Dissipation: 850mW; Code Arduino: U0052; On-State Resistance: 95mR; Max Output Current: 2.5A; Device Type: PWR SWITCH; Fault Protection: Over Temperature; Max Supply Current: 1uA
footprint PQFN50P300X300X55_HS-21L (PQFN, 20-Leads, Body 3.00x3.00mm, Pitch 0.50mm, Thermal Pad 1.69x2.59mm, IPC High Density)
pins: 1 GND (power), 2 IN (power), 3 IN (power), 4 ~{EN1} (in), 5 ~{EN2} (in), 6 ~{FLAG2} (out), 7 ILIM (out), 8 OUT2 (out), 9 OUT1 (out), 10 ~{FLAG1} (out), 11 PAD

## U0053-A.2
designator U?, comment CS42L52-CNZ-A.7
IC CODEC STER HDPN & SPKR 40QFN; Manufacturer: Cirrus Logic; Number of A/D Converters: 1; Operating Supply Voltage: 2.5V; Code Arduino: U0053; Interface: Serial,I2C,SPI; Resolution: 24b; Sampling Rate: 96KS/s
footprint QFN127P600-8N
pins: 1 SDA (io), 2 SCL (in), 3 AD0 (in), 4 SPK_OUTA+ (out), 5 VP (power), 6 SPK_OUTA- (out), 7 SPK_OUTB+ (out), 8 VP (power), 9 SPK_OUTB- (out), 10 -VHPFILT (out), 11 FLYN (out), 12 FLYP (out), 13 +VHP (power), 14 HP/LINE_OUTB (out), 15 HP/LINE_OUTA (out), 16 VA (power), 17 AGND (power), 18 FILT+ (out), 19 VQ (out), 20 MICBIAS (out), 21 AIN4A (in), 22 AIN4B (in), 23 AIN3A (in), 24 AIN3B (in), 25 AIN2A (in), 26 AIN2B (in), 27 AFILTA (out), 28 AFILTB (out), 29 AIN1A (in), 30 AIN1B (in), 31 SPKR/HP (in), 32 ~{RESET} (in), 33 VL (power), 34 VD (power), 35 DGND (power), 36 SDOUT (out), 37 MCLK (in), 38 SCLK (io), 39 SDIN (in), 40 LRCLK (io), 41 GND (power)

## U0056-A.2
designator U?, comment FXMA2102L8X-A.2
IC TRANSLATOR/BUFF/REPEAT 8-MLP; Manufacturer: On Semiconductor; Manufacturer: ON Semiconductor / Fairchild; Max Power Dissipation: 129mW; Quiescent Current: 5uA; Device Type: TRANSLATOR BIDIR; Code Arduino: U0056; Number of Bits: 2; Logic Function: Translator,Buffer; Max Supply Voltage: 5.5V; Min Supply Voltage: 1.65V; Low Level Output Current: 6mA; Output Type: Voltage; Frequency: 50MHz; Propagation Delay: 105ns; Turn-On Delay Time: 1ns; Nominal Supply Current: 2uA
footprint MicroPak-8 (8- Lead MicroPak™, 1.6 mm Wide)
pins: 1 VCCA (power), 2 A0 (io), 3 A1 (io), 4 GND (power), 5 OE (in), 6 B1 (io), 7 B0 (io), 8 VCCB (power)

## U0114-A.1
designator U?, comment TJA1049T/3J
IC CAN TRANSCEIVER 1Mbps STBY 5.25V SOIC8; Manufacturer: NXP; Manufacturer: NXP Semiconductors; Code Arduino: U0114; Data Rate: 5Mbps; Number of Transceivers: 1; Simplex/Duplex: Half Duplex; Receiver Hysteresis: 300mV; Min Supply Voltage: 4.75V
footprint TJA1049T_3J-Footprint-1
pins: 1 TX (in), 2 GND (power), 3 VDD (power), 4 RX (out), 5 S/VIO, 6 CANL, 7 CANH, 8 STB (in)

## UT0013-A.1
designator R410_D+?, comment CMP-018-0005-A.3  (value not drawn)  (no BOM)
Test point 1.00mm
footprint TP-1.00MM
pins: X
